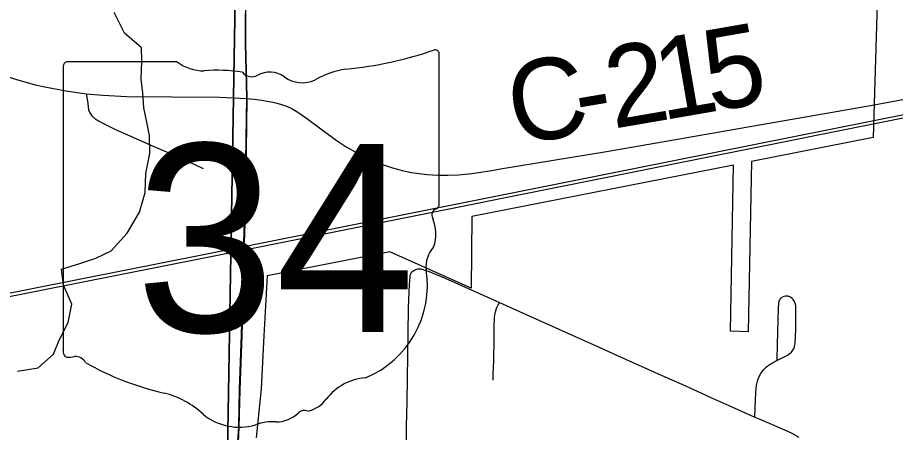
# Model space of a CAD drawing. Extents: x 0 to 34, y 0 to 22.
# Drawn here: x 5.615 to 6.231, y 17.848 to 18.139 of the extents above; entities that cross this region are included whole.
import ezdxf

# ---------------------------------------------------------------- set-up
doc = ezdxf.new("R2010")
doc.units = 0
for name, color, linetype in [('GM_X_City_Street', 7, 'Continuous'), ('GM_X_Corporation', 7, 'Continuous'), ('GM_X_County_Road', 7, 'Continuous'), ('GM_X_County_Road_Text', 7, 'Continuous'), ('GM_X_Minor_River', 7, 'Continuous'), ('GM_X_Rail_Line', 7, 'Continuous'), ('GM_X_State_Location', 7, 'Continuous'), ('GM_X_State_Route', 7, 'Continuous'), ('GM_X_State_Shield', 7, 'Continuous')]:
    doc.layers.add(name, color=color, linetype=linetype)

msp = doc.modelspace()

# ---------------------------------------------------------------- linework, layer by layer
at = {"layer": 'GM_X_City_Street'}
for points in [[(5.88824, 17.83286), (5.88829, 17.84147), (5.88835, 17.85265), (5.88876, 17.87005), (5.88928, 17.90241), (5.88933, 17.91752), (5.88969, 17.93598), (5.89032, 17.95207), (5.89077, 17.95752), (5.89091, 17.95831), (5.89116, 17.9592), (5.89145, 17.96), (5.89185, 17.96067), (5.89295, 17.96182)], [(6.13262, 17.85914), (6.13298, 17.8712), (6.13323, 17.87588), (6.13352, 17.87925), (6.13385, 17.8816), (6.13419, 17.88354), (6.13467, 17.88536), (6.1353, 17.88709), (6.13671, 17.88985), (6.13854, 17.89234), (6.14076, 17.89449), (6.14327, 17.8963), (6.14759, 17.89875), (6.15541, 17.90257), (6.15649, 17.90324), (6.15744, 17.90399), (6.15803, 17.90453), (6.15871, 17.90532), (6.15922, 17.90602), (6.15969, 17.90687), (6.16004, 17.90762), (6.16034, 17.9086), (6.1606, 17.90973), (6.16076, 17.91105), (6.16122, 17.92035), (6.16143, 17.92903), (6.16136, 17.93587), (6.16125, 17.93708), (6.16105, 17.93834), (6.16047, 17.94012), (6.1595, 17.94169), (6.15863, 17.94257), (6.15761, 17.94326), (6.15588, 17.94392), (6.15403, 17.94403), (6.15285, 17.94374), (6.15176, 17.94322), (6.151, 17.94263), (6.15039, 17.94198), (6.14992, 17.94124), (6.14951, 17.94038), (6.14925, 17.93954), (6.14906, 17.9386), (6.14885, 17.93611), (6.14814, 17.91003), (6.14795, 17.89943)], [(5.9497, 17.91397), (5.94982, 17.91986), (5.94983, 17.92406), (5.94993, 17.927), (5.95003, 17.92903), (5.95029, 17.93085), (5.95049, 17.93192), (5.9507, 17.933), (5.95119, 17.93451), (5.95172, 17.93602), (5.95257, 17.93782), (5.95354, 17.93962)], [(5.94895, 17.88513), (5.94906, 17.88933), (5.94924, 17.8939), (5.94941, 17.89889), (5.9497, 17.91397)]]:
    msp.add_lwpolyline(points, dxfattribs=at)
at = {"layer": 'GM_X_Corporation'}
for points in [[(4.77752, 18.58568), (5.77487, 18.55224), (5.75845, 17.5867), (5.75807, 17.55374), (4.7439, 17.58074)], [(5.77565, 18.58596), (6.72002, 18.57343), (6.70042, 17.56893), (5.75845, 17.5867), (5.77487, 18.55224)]]:
    msp.add_lwpolyline(points, close=True, dxfattribs=at)
for points in [[(6.22975, 18.53314), (6.21631, 18.07885), (6.2156, 18.05515), (6.13025, 18.03834), (6.12782, 17.91893), (6.11542, 17.91933), (6.11761, 18.03585), (5.9341, 17.9997), (5.93354, 17.94953), (5.87665, 17.97512), (5.79059, 17.95817), (5.78832, 17.91607), (5.78633, 17.87912), (5.78286, 17.8446)], [(5.76998, 17.84187), (5.77056, 17.85271), (5.77123, 17.87888), (5.77256, 17.91691), (5.77374, 17.95725), (5.77401, 17.97458), (5.77515, 18.00991), (5.77617, 18.083), (5.7754, 18.12096), (5.77545, 18.14212)], [(5.77545, 18.14212), (5.7754, 18.12096), (5.77617, 18.083), (5.77515, 18.00991), (5.77401, 17.97458), (5.77374, 17.95725), (5.77256, 17.91691), (5.77123, 17.87888), (5.77056, 17.85271), (5.76998, 17.84187)]]:
    msp.add_lwpolyline(points, dxfattribs=at)
at = {"layer": 'GM_X_County_Road'}
for p, q in [((6.09956, 17.87388), (6.11425, 17.86733)), ((6.11425, 17.86733), (6.13262, 17.85914))]:
    msp.add_line(p, q, dxfattribs=at)
for points in [[(5.7764, 18.08244), (5.77563, 18.12041), (5.77568, 18.14156), (5.77669, 18.17137), (5.77738, 18.18545)], [(6.21638, 18.07813), (6.23636, 18.08179), (6.27308, 18.08871), (6.30416, 18.09495), (6.34802, 18.10376), (6.39252, 18.11256), (6.44133, 18.12196), (6.48641, 18.13103), (6.53525, 18.1404), (6.54984, 18.14361), (6.56013, 18.14618), (6.5673, 18.14836), (6.57261, 18.15023), (6.58415, 18.15489), (6.59278, 18.15833), (6.5992, 18.16057), (6.60809, 18.16323), (6.6183, 18.16579), (6.6377, 18.17004), (6.68086, 18.17925), (6.71977, 18.18742)], [(5.66375, 18.08587), (5.66389, 18.08485), (5.66466, 18.07888), (5.66533, 18.07466), (5.66622, 18.07234), (5.66758, 18.07028), (5.6699, 18.06826), (5.67217, 18.06681), (5.67471, 18.06544), (5.68417, 18.0608), (5.69045, 18.05798), (5.71048, 18.04918), (5.72821, 18.04151), (5.74068, 18.03585), (5.74574, 18.03346)], [(5.76959, 17.83365), (5.77022, 17.84132), (5.77079, 17.85216), (5.77147, 17.87833), (5.77279, 17.91635), (5.77398, 17.95669), (5.77424, 17.97402), (5.77539, 18.00936), (5.7764, 18.08244)], [(5.7764, 18.08244), (5.78148, 18.08195), (5.78679, 18.08133), (5.79043, 18.0807), (5.79463, 18.07991), (5.79731, 18.07932), (5.79998, 18.0786), (5.80342, 18.07741), (5.80538, 18.07661), (5.8073, 18.07566), (5.81205, 18.07289), (5.81817, 18.06874), (5.82909, 18.06055), (5.83958, 18.05273), (5.84535, 18.04898), (5.85295, 18.04463), (5.8602, 18.04096), (5.86707, 18.03792), (5.8706, 18.03656), (5.87353, 18.03554), (5.87834, 18.03399), (5.88191, 18.033), (5.88516, 18.03214), (5.8886, 18.03137), (5.89178, 18.03069), (5.89537, 18.03012), (5.90283, 18.02921), (5.91033, 18.02875), (5.91721, 18.02871), (5.92471, 18.02908), (5.93401, 18.03004), (5.94819, 18.03213), (5.95414, 18.03311)], [(5.95414, 18.03311), (6.02849, 18.0454), (6.06891, 18.05234), (6.14665, 18.06588), (6.18032, 18.07173), (6.21638, 18.07813)], [(5.89295, 17.96182), (5.89481, 17.9627), (5.89547, 17.96294), (5.89614, 17.96312), (5.89727, 17.96318), (5.89824, 17.96307), (5.89986, 17.96271), (5.90118, 17.96229), (5.90256, 17.9618), (5.90424, 17.96121), (5.90579, 17.96062), (5.91541, 17.95654), (5.93369, 17.94831)], [(5.93369, 17.94831), (5.94, 17.94556), (5.95354, 17.93962)], [(5.95354, 17.93962), (5.96762, 17.9332), (6.00658, 17.91564), (6.02125, 17.90908), (6.03518, 17.90283), (6.06903, 17.88775)], [(6.06903, 17.88775), (6.08137, 17.88218), (6.09773, 17.8747), (6.09956, 17.87388)], [(6.13262, 17.85914), (6.13598, 17.85771), (6.14422, 17.85417), (6.15015, 17.85172), (6.15461, 17.84985), (6.15852, 17.84799), (6.16062, 17.84685), (6.16222, 17.84589), (6.16303, 17.84529), (6.16353, 17.84482)]]:
    msp.add_lwpolyline(points, dxfattribs=at)
at = {"layer": 'GM_X_Minor_River'}
for points in [[(5.70395, 18.07593), (5.7034, 18.08657), (5.70207, 18.09608), (5.70269, 18.10859), (5.70249, 18.11809), (5.69055, 18.12819), (5.68325, 18.14275)], [(5.61545, 17.8913), (5.6299, 17.89368), (5.64071, 17.90333), (5.64469, 17.91312), (5.651, 17.92553), (5.65352, 17.93838), (5.64771, 17.95178), (5.64641, 17.96281), (5.65976, 17.9671), (5.67045, 17.97069), (5.68116, 17.9758), (5.6924, 17.9881), (5.70102, 18.00274), (5.70509, 18.0167), (5.70534, 18.02998), (5.70827, 18.04396), (5.70813, 18.05649), (5.70604, 18.06602), (5.70395, 18.07593)]]:
    msp.add_lwpolyline(points, dxfattribs=at)
at = {"layer": 'GM_X_Rail_Line'}
for points in [[(2.1, 17.25784), (2.18393, 17.27433), (2.73729, 17.38072), (3.32149, 17.49791), (3.96117, 17.62281), (4.55539, 17.74), (5.15654, 17.85642), (5.77541, 17.979), (6.33417, 18.09079), (6.90219, 18.20181), (7.3492, 18.28816), (7.42386, 18.30272), (8.00923, 18.41684), (8.46231, 18.50822), (8.9, 18.59581)], [(2.1, 17.25547), (2.18438, 17.27205), (2.73774, 17.37844), (3.32194, 17.49563), (3.96162, 17.62053), (4.55584, 17.73772), (5.15699, 17.85414), (5.77586, 17.97672), (6.33462, 18.08851), (6.90263, 18.19953), (7.34964, 18.28588), (7.42431, 18.30044), (8.00968, 18.41456), (8.46244, 18.50563), (8.9, 18.59339)]]:
    msp.add_lwpolyline(points, dxfattribs=at)
at = {"layer": 'GM_X_State_Route'}
for points in [[(5.5201, 18.13614), (5.52482, 18.134), (5.54629, 18.12418), (5.58195, 18.10791), (5.59348, 18.10318), (5.59995, 18.10082), (5.60815, 18.09791), (5.61482, 18.09574), (5.62069, 18.09413), (5.62792, 18.09219), (5.63463, 18.09071), (5.64933, 18.08786), (5.66375, 18.08587), (5.67534, 18.08485), (5.69213, 18.08399), (5.72385, 18.08366), (5.75739, 18.08332), (5.7764, 18.08244)], [(5.7764, 18.08244), (5.77539, 18.00936), (5.77424, 17.97402), (5.77398, 17.95669), (5.77279, 17.91635), (5.77147, 17.87833), (5.77079, 17.85216), (5.77022, 17.84132), (5.76959, 17.83365)]]:
    msp.add_lwpolyline(points, dxfattribs=at)
at = {"layer": 'GM_X_State_Shield'}
for p, q in [((5.72737, 18.1083), (5.65015, 18.1083)), ((5.91122, 18.00858), (5.91122, 18.11326)), ((5.64756, 18.10486), (5.64756, 17.90474)), ((5.9112, 18.0086), (5.91122, 18.00858))]:
    msp.add_line(p, q, dxfattribs=at)
for centre, radius, start, end in [((5.8173, 18.38114), 0.27962, 275.84447, 288.90645), ((5.9083, 18.1137), 0.00294, 351.86209, 97.738), ((5.65058, 18.10529), 0.00305, 98.1301, 188.1301), ((5.74576, 18.13154), 0.02963, 231.61951, 271.11188), ((5.75558, 17.99595), 0.10636, 80.48669, 94.98827), ((5.85297, 18.04718), 0.05625, 97.34618, 120.76885), ((5.77973, 18.10632), 0.00855, 219.79206, 297.10237), ((5.79227, 18.08319), 0.01777, 54.46668, 119.14113), ((5.81521, 18.11492), 0.02138, 233.85621, 294.82819), ((5.91054, 18.00089), 0.00454, 107.94398, 210.33697), ((5.90809, 18.00817), 0.00314, 289.60381, 7.73413), ((5.88164, 17.98766), 0.02727, 340.03296, 23.64957), ((5.92174, 17.96477), 0.01984, 136.8065, 186.92959), ((5.83296, 17.95145), 0.06994, 292.30889, 8.98584), ((5.6506, 17.9043), 0.00308, 171.95839, 258.30661), ((5.65107, 17.92478), 0.02352, 267.33899, 280.60386), ((5.65588, 17.89319), 0.00848, 29.74838, 93.27175), ((5.76294, 18.07299), 0.20192, 240.41292, 257.1985), ((5.86245, 17.84856), 0.0383, 94.40312, 142.57675), ((5.70274, 17.81484), 0.06318, 47.18416, 75.83597), ((5.81392, 17.88534), 0.0226, 282.87319, 323.27711), ((5.79716, 17.87722), 0.02136, 268.77702, 315.54927), ((5.81649, 17.85783), 0.00601, 65.75173, 132.64842), ((5.77107, 17.8922), 0.04009, 230.70037, 286.29184), ((5.79424, 17.82301), 0.03294, 85.69512, 111.20995)]:
    msp.add_arc(centre, radius, start, end, dxfattribs=at)

# ---------------------------------------------------------------- texts
at = {"layer": 'GM_X_County_Road_Text'}
for s, rotation, p in [('5', 9.83697, (6.10167, 18.07304)), ('1', 9.82638, (6.06745, 18.06711)), ('2', 9.75146, (6.03315, 18.06122)), ('C', 9.425, (5.9643, 18.04973)), ('-', 9.58577, (6.01017, 18.05734))]:
    msp.add_text(s, height=0.05682, rotation=rotation, dxfattribs=at).set_placement(p)
at = {"layer": 'GM_X_State_Location'}
for s, p in [('s', (5.77642, 17.9915)), ('r', (5.77641, 17.9915))]:
    msp.add_text(s, height=0.000189, dxfattribs=at).set_placement(p)
msp.add_text('34', height=0.000189, rotation=0.00001, dxfattribs=at).set_placement((5.72872, 17.97772))
at = {"layer": 'GM_X_State_Shield'}
msp.add_text('34', height=0.131836, dxfattribs=at).set_placement((5.69814, 17.91885))

doc.saveas('drawing.dxf')
